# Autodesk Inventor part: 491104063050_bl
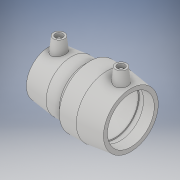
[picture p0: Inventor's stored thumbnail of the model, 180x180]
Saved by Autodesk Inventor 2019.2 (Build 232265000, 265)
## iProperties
Created: 2017-06
Part Number: 491104063050_bl
Material: Generic
Description: PLASSON REDUCING COUPLER 63-50
Document SubType Name: Modeling
Designer: KIM
Mass: 54.8237 g
Surface Area: 155.252 cm^2
Volume: 54.8237 cm^3
Density: 1 g/cm^3
Appearance: Default
Author: KIM
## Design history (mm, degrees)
derived "491104 (Type 3).ipt"
feature "Solid1::491104 (Type 3).ipt" dims "ScaleForDerivedMember" = 10
tag "TaggingFeature1"
body "Solid1"
other parameters: "D_1" = 68 [user parameter], "d_2" = 12 [user parameter], "L_1" = 54 [user parameter], "d_" = 63 [user parameter], "A_" = 56 [user parameter], "D_" = 82 [user parameter], "d2" = 68 [user parameter], "d5" = 61.2 [user parameter], "d8" = 168 deg [user parameter], "d11" = 6.66667 [user parameter], "d14" = 17.6296 [user parameter], "d19" = 2.5 [user parameter], "d20" = 168 deg [user parameter], "d22" = 108.92847 [user parameter], "d25" = 135 deg [user parameter], "d30" = 15 [user parameter], "d31" = 41.8 [user parameter], "d34" = 6 deg [user parameter], "d35" = 15 [user parameter], "d38" = 22.5 [user parameter], "d39" = 5 deg [user parameter], "d41" = 4 [user parameter], "d42" = 14 [user parameter], "d43" = 0 [user parameter], "d45" = 4 [user parameter], "d46" = 14 [user parameter], "d47" = 0 [user parameter], "d48" = 68 [user parameter], "d49" = 63 [user parameter], "d50" = 82 [user parameter], "d52" = 45 [user parameter], "d53" = 21.6 [user parameter], "d54" = 7.2 [user parameter], "d55" = 168 deg [user parameter], "d56" = 32.4 [user parameter], "d57" = 54 [user parameter], "d58" = 73.8 [user parameter], "d59" = 2.5 [user parameter], "d60" = 135 deg [user parameter], "d61" = 56 [user parameter], "d62" = 15 [user parameter], "d64" = 4 [user parameter], "d66" = 5 deg [user parameter], "d67" = 14 [user parameter], "d68" = 0 [user parameter], "d69" = 41.8 [user parameter], "d70" = 68 [user parameter], "d71" = 82 [user parameter], "d73" = 77.08 [user parameter], "d76" = 2.5 [user parameter], "d77" = 168 deg [user parameter], "d78" = 63 [user parameter], "d79" = 2.5 [user parameter], "d80" = 54 [user parameter], "d81" = 45 [user parameter], "d82" = 63.92 [user parameter], "d83" = 120 deg [user parameter], "d88" = 15 [user parameter], "d89" = 21.35 [user parameter], "d90" = 5 deg [user parameter], "d92" = 4 [user parameter], "d93" = 14 [user parameter], "d94" = 0 [user parameter], "d95" = 3 [user parameter], "d96" = 0 [user parameter], "d97" = 3 [user parameter], "d98" = 0 [user parameter], "d99" = 14.5 [user parameter], "d100" = 3.625 [user parameter], "d101" = 62.0024 [user parameter], "d102" = 20 deg [user parameter], "d103" = 15.66 [user parameter], "d104" = 3.915 [user parameter], "d105" = 74.7676 [user parameter], "d106" = 3.60705 [user parameter], "d107" = 3 [user parameter], "d108" = 0 [user parameter], "d109" = 3 [user parameter], "d110" = 0 [user parameter]
